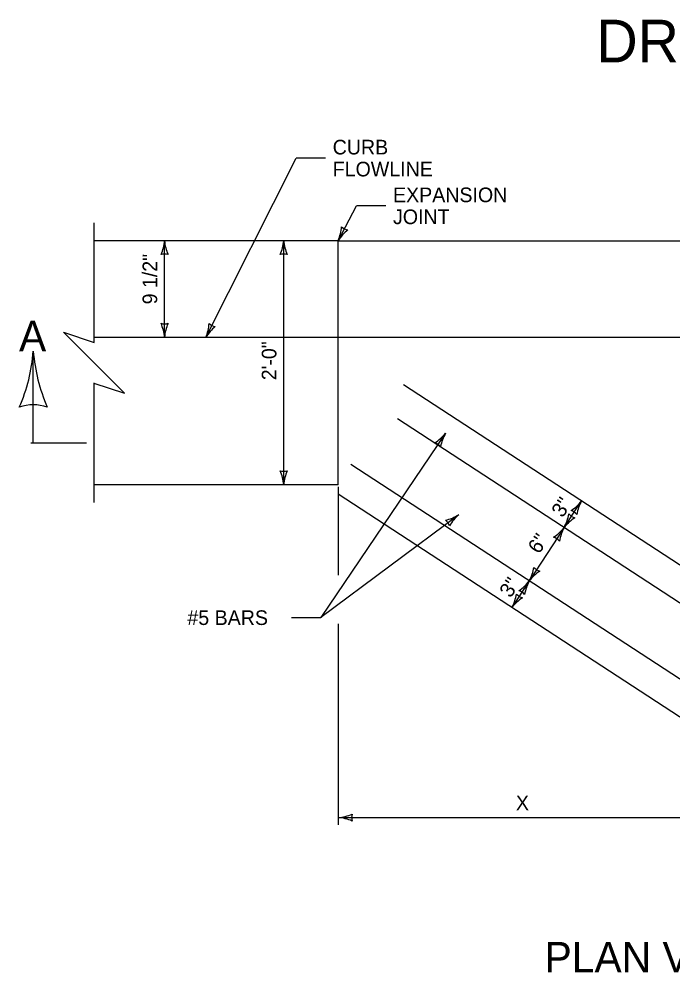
# Model space of a CAD drawing. Extents: x 49991.4 to 50048.3, y 49987.6 to 50018.3.
# Drawn here: x 50033.9 to 50039.25, y 50010.48 to 50018.29 of the extents above; entities that cross this region are included whole.
import ezdxf

# ---------------------------------------------------------------- set-up
doc = ezdxf.new("R2010")
doc.units = 0
doc.layers.add('Level 1', color=7, linetype='Continuous')

# ---------------------------------------------------------------- blocks, each defined once
blk = doc.blocks.new('Arr1')
at = {"layer": 'Level 1'}
for centre, radius, start, end in [((0.0003380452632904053, 0.004588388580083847), 0.0046008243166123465, 246.13281152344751, 265.7863990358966), ((-0.002683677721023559, 2.2053718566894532e-10), 0.0012211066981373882, 341.8194575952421, 18.18051657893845), ((0.00040889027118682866, -0.004871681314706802), 0.004888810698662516, 94.79770847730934, 113.28308350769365)]:
    blk.add_arc(centre, radius, start, end, dxfattribs=at)

msp = doc.modelspace()

# ---------------------------------------------------------------- linework, layer by layer
at = {"layer": 'Level 1'}
for p, q in [((50035.42748712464, 50015.6844356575), (50036.16552598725, 50017.154326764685)), ((50036.40552598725, 50017.154326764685), (50036.16552598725, 50017.154326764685)), ((50036.51070081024, 50016.47753518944), (50036.65959989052, 50016.763159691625)), ((50036.89959989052, 50016.763159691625), (50036.65959989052, 50016.763159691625)), ((50036.51070081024, 50016.47753518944), (50034.51070081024, 50016.47753518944)), ((50035.08820307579, 50015.68586852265), (50035.08820307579, 50016.47753518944)), ((50036.06452940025, 50014.47753518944), (50036.06452940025, 50016.47753518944)), ((50036.51070081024, 50014.47753518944), (50036.51070081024, 50016.47753518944)), ((50036.51070081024, 50016.47753518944), (50045.510700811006, 50016.47753518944)), ((50034.51070081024, 50015.68586852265), (50047.510700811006, 50015.68586852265)), ((50034.013200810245, 50014.820673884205), (50034.013200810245, 50015.570673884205)), ((50039.88927783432, 50013.44020185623), (50037.04538776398, 50015.29663009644)), ((50039.79420386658, 50013.19060936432), (50036.99594192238, 50015.01725257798)), ((50037.38982426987, 50014.89936443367), (50036.36780330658, 50013.38742420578)), ((50033.99236747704, 50014.820673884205), (50034.44820081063, 50014.820673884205)), ((50039.60515051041, 50012.69020185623), (50036.61516706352, 50014.64199660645)), ((50036.51070081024, 50014.47753518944), (50034.51070081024, 50014.47753518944)), ((50036.51070081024, 50014.45920185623), (50036.51070081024, 50013.734485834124)), ((50039.51070081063, 50012.44020185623), (50036.51070081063, 50014.39853518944)), ((50038.36121376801, 50014.12603345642), (50038.50386754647, 50014.34456690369)), ((50037.49793363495, 50014.231512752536), (50036.36780330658, 50013.38742420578)), ((50038.36121376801, 50014.12603345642), (50037.9330199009, 50013.47007689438)), ((50036.12780330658, 50013.38742420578), (50036.36780330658, 50013.38742420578)), ((50036.51070081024, 50013.336848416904), (50036.51070081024, 50011.68914241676)), ((50036.51070081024, 50011.74914241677), (50039.51070081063, 50011.74914241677))]:
    msp.add_line(p, q, dxfattribs=at)
msp.add_lwpolyline([(50034.51070081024, 50014.33170185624), (50034.51070081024, 50015.30964591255), (50034.51029361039, 50015.30964591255), (50034.76070081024, 50015.22753518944), (50034.26070081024, 50015.72753518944), (50034.51070081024, 50015.64420185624), (50034.51070081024, 50016.62336852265)], dxfattribs=at)
for centre, radius, start, end in [((50036.17253073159, 50016.61924313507), 0.36666080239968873, 337.26419985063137, 355.74957488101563), ((50036.17253073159, 50016.61924313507), 0.36666080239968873, 337.26419985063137, 355.74957488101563), ((50036.80413405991, 50016.2959736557), 0.345061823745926, 128.59930289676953, 148.25289040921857), ((50036.80413405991, 50016.2959736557), 0.345061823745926, 128.59930289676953, 148.25289040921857), ((50036.6037440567, 50016.65601463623), 0.09158300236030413, 224.28594896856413, 260.6470079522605), ((50036.6037440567, 50016.65601463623), 0.09158300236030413, 224.28594896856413, 260.6470079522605), ((50034.744073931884, 50016.502888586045), 0.345061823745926, 336.1328115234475, 355.7863990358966), ((50034.744073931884, 50016.502888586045), 0.345061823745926, 336.1328115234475, 355.7863990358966), ((50035.45357917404, 50016.50820196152), 0.36666080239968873, 184.79770847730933, 203.28308350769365), ((50035.45357917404, 50016.50820196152), 0.36666080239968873, 184.79770847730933, 203.28308350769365), ((50035.72040025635, 50016.502888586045), 0.345061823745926, 336.1328115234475, 355.7863990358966), ((50035.72040025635, 50016.502888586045), 0.345061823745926, 336.1328115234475, 355.7863990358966), ((50036.42990549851, 50016.50820196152), 0.36666080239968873, 184.79770847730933, 203.28308350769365), ((50036.42990549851, 50016.50820196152), 0.36666080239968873, 184.79770847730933, 203.28308350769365), ((50035.08820305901, 50016.276259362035), 0.09158300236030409, 71.81945759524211, 108.18051657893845), ((50035.08820305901, 50016.276259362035), 0.09158300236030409, 71.81945759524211, 108.18051657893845), ((50036.06452938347, 50016.276259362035), 0.09158300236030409, 71.81945759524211, 108.18051657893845), ((50036.06452938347, 50016.276259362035), 0.09158300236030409, 71.81945759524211, 108.18051657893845), ((50034.722826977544, 50015.65520175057), 0.36666080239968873, 4.797708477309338, 23.28308350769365), ((50035.08820309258, 50015.887144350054), 0.0915830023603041, 251.8194575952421, 288.18051657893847), ((50035.08820309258, 50015.887144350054), 0.0915830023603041, 251.8194575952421, 288.18051657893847), ((50034.722826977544, 50015.65520175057), 0.36666080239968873, 4.797708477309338, 23.28308350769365), ((50035.4323322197, 50015.66051512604), 0.345061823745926, 156.13281152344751, 175.78639903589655), ((50035.4323322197, 50015.66051512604), 0.345061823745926, 156.13281152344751, 175.78639903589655), ((50035.08719941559, 50015.820980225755), 0.36666080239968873, 338.1362777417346, 356.6216527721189), ((50035.08719941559, 50015.820980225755), 0.36666080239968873, 338.1362777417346, 356.6216527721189), ((50035.723649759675, 50015.50736122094), 0.34506182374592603, 129.47138078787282, 149.12496830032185), ((50035.723649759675, 50015.50736122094), 0.34506182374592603, 129.47138078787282, 149.12496830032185), ((50035.517803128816, 50015.864310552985), 0.0915830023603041, 225.15802685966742, 261.51908584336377), ((50035.517803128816, 50015.864310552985), 0.0915830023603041, 225.15802685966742, 261.51908584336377), ((50037.11891960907, 50015.11308932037), 0.3450618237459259, 302.07543506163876, 321.7290225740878), ((50037.11891960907, 50015.11308932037), 0.3450618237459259, 302.07543506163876, 321.7290225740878), ((50037.11891960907, 50015.11308932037), 0.3450618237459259, 302.07543506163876, 321.7290225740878), ((50037.11891960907, 50015.11308932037), 0.3450618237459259, 302.07543506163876, 321.7290225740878), ((50037.70970412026, 50014.720152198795), 0.36666080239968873, 150.74033201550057, 169.2257070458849), ((50037.70970412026, 50014.720152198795), 0.36666080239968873, 150.74033201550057, 169.2257070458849), ((50037.70970412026, 50014.720152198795), 0.36666080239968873, 150.74033201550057, 169.2257070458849), ((50037.70970412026, 50014.720152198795), 0.36666080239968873, 150.74033201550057, 169.2257070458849), ((50037.27710519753, 50014.73261201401), 0.0915830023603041, 37.762081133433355, 74.1231401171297), ((50037.27710519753, 50014.73261201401), 0.0915830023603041, 37.762081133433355, 74.1231401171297), ((50037.27710519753, 50014.73261201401), 0.0915830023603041, 37.762081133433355, 74.1231401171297), ((50037.27710519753, 50014.73261201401), 0.0915830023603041, 37.762081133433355, 74.1231401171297), ((50035.699153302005, 50014.44686841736), 0.36666080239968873, 4.797708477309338, 23.28308350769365), ((50036.06452941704, 50014.67881101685), 0.0915830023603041, 251.8194575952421, 288.18051657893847), ((50036.06452941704, 50014.67881101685), 0.0915830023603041, 251.8194575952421, 288.18051657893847), ((50035.699153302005, 50014.44686841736), 0.36666080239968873, 4.797708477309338, 23.28308350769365), ((50036.40865854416, 50014.45218179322), 0.345061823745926, 156.13281152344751, 175.78639903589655), ((50036.40865854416, 50014.45218179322), 0.345061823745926, 156.13281152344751, 175.78639903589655), ((50038.22955971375, 50014.553906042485), 0.3450618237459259, 302.9972019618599, 322.6507894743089), ((50038.22955971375, 50014.553906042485), 0.3450618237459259, 302.9972019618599, 322.6507894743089), ((50038.8265890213, 50014.1705238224), 0.3666608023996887, 151.66209891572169, 170.147473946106), ((50038.8265890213, 50014.1705238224), 0.3666608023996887, 151.66209891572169, 170.147473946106), ((50038.39384563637, 50014.1760227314), 0.0915830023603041, 38.68384803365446, 75.0449070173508), ((50038.39384563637, 50014.1760227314), 0.0915830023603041, 38.68384803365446, 75.0449070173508), ((50037.312317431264, 50014.522398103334), 0.34506182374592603, 282.8886764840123, 302.5422639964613), ((50037.312317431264, 50014.522398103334), 0.34506182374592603, 282.8886764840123, 302.5422639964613), ((50037.33667292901, 50014.11106797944), 0.0915830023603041, 18.575322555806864, 54.9363815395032), ((50037.33667292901, 50014.11106797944), 0.0915830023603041, 18.575322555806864, 54.9363815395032), ((50037.74114709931, 50013.957127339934), 0.36666080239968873, 131.5535734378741, 150.0389484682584), ((50037.74114709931, 50013.957127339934), 0.36666080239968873, 131.5535734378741, 150.0389484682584), ((50038.03849229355, 50014.300076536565), 0.36666080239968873, 331.6620989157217, 350.147473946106), ((50038.03849229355, 50014.300076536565), 0.36666080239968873, 331.6620989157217, 350.147473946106), ((50038.63552160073, 50013.91669431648), 0.3450618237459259, 122.9972019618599, 142.65078947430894), ((50038.63552160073, 50013.91669431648), 0.3450618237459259, 122.9972019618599, 142.65078947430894), ((50038.4712356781, 50014.29457762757), 0.0915830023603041, 218.68384803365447, 255.0449070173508), ((50038.4712356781, 50014.29457762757), 0.0915830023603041, 218.68384803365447, 255.0449070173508), ((50038.086905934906, 50014.3353725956), 0.34506182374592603, 302.9972019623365, 322.65078947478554), ((50038.086905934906, 50014.3353725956), 0.34506182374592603, 302.9972019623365, 322.65078947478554), ((50038.68393524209, 50013.95199037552), 0.3666608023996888, 151.6620989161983, 170.1474739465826), ((50038.68393524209, 50013.95199037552), 0.3666608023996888, 151.6620989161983, 170.1474739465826), ((50038.25119185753, 50013.95748928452), 0.09158300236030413, 38.68384803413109, 75.04490701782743), ((50038.25119185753, 50013.95748928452), 0.09158300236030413, 38.68384803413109, 75.04490701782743), ((50037.75295220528, 50013.862653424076), 0.3666608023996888, 331.6620989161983, 350.14747394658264), ((50037.75295220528, 50013.862653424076), 0.3666608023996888, 331.6620989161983, 350.14747394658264), ((50038.18569558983, 50013.85715451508), 0.0915830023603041, 218.68384803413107, 255.04490701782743), ((50038.18569558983, 50013.85715451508), 0.0915830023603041, 218.68384803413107, 255.04490701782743), ((50038.34998151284, 50013.479271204), 0.34506182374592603, 122.99720196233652, 142.65078947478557), ((50038.34998151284, 50013.479271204), 0.34506182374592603, 122.99720196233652, 142.65078947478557), ((50037.80136584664, 50013.8979494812), 0.3450618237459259, 302.9972019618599, 322.6507894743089), ((50037.80136584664, 50013.8979494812), 0.3450618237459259, 302.9972019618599, 322.6507894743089), ((50038.39839515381, 50013.51456726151), 0.3666608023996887, 151.66209891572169, 170.147473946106), ((50038.39839515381, 50013.51456726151), 0.3666608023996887, 151.66209891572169, 170.147473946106), ((50037.61029842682, 50013.644119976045), 0.36666080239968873, 331.6620989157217, 350.147473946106), ((50037.61029842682, 50013.644119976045), 0.36666080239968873, 331.6620989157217, 350.147473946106), ((50038.043041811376, 50013.638621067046), 0.0915830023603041, 218.68384803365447, 255.0449070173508), ((50038.043041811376, 50013.638621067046), 0.0915830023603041, 218.68384803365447, 255.0449070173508), ((50037.96565176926, 50013.5200661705), 0.0915830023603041, 38.68384803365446, 75.0449070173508), ((50037.96565176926, 50013.5200661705), 0.0915830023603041, 38.68384803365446, 75.0449070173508), ((50038.207327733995, 50013.26073775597), 0.3450618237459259, 122.9972019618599, 142.65078947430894), ((50038.207327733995, 50013.26073775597), 0.3450618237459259, 122.9972019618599, 142.65078947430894), ((50036.48003403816, 50012.11451851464), 0.36666080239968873, 274.79770847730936, 293.2830835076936), ((50036.48003403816, 50012.11451851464), 0.36666080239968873, 274.79770847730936, 293.2830835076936), ((50036.71197663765, 50011.749142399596), 0.0915830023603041, 161.81945759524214, 198.18051657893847), ((50036.71197663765, 50011.749142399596), 0.0915830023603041, 161.81945759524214, 198.18051657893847), ((50036.48534741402, 50011.40501327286), 0.345061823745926, 66.13281152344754, 85.7863990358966), ((50036.48534741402, 50011.40501327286), 0.345061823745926, 66.13281152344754, 85.7863990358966)]:
    msp.add_arc(centre, radius, start, end, dxfattribs=at)

# ---------------------------------------------------------------- block references
at = {"layer": 'Level 1', "xscale": 300, "yscale": 300, "rotation": 90}
msp.add_blockref('Arr1', (50034.01320080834, 50015.57067389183), dxfattribs=at)

# ---------------------------------------------------------------- texts
at = {"layer": 'Level 1'}
for s, height, p in [('DROP INLET APRON', 0.35, (50038.62579227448, 50017.93874029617)), ('CURB', 0.12000000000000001, (50036.465525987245, 50017.184326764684)), ('FLOWLINE', 0.12000000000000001, (50036.465525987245, 50017.00432676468)), ('EXPANSION', 0.12000000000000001, (50036.95959989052, 50016.79315969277)), ('JOINT', 0.12000000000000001, (50036.95959989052, 50016.613159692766)), ('A', 0.25, (50033.89639440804, 50015.570673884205)), ('#5 BARS', 0.12000000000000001, (50035.27548496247, 50013.32742420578)), ('X', 0.11979166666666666, (50037.96634294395, 50011.80924658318)), ('PLAN VIEW - DROP INLET APRON', 0.25, (50038.20096376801, 50010.4789537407))]:
    msp.add_text(s, height=height, dxfattribs=at).set_placement(p)
for s, height, rotation, p in [('9 1/2"', 0.11979166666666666, 90, (50035.02809890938, 50015.95569180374)), ('2\'-0"', 0.11979166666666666, 90, (50036.00442523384, 50015.33361200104)), ('3"', 0.11979166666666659, 56.864390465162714, (50038.34933948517, 50014.20071739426)), ('6"', 0.11979166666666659, 56.864390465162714, (50038.156096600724, 50013.90294497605)), ('3"', 0.11979166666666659, 56.864390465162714, (50037.92301229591, 50013.543381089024))]:
    msp.add_text(s, height=height, rotation=rotation, dxfattribs=at).set_placement(p)

doc.saveas('drawing.dxf')
